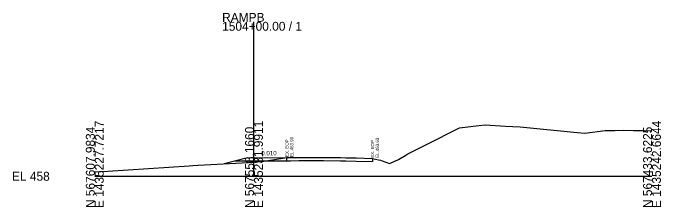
# Model space of a CAD drawing. Extents: x 1431908 to 1449087, y 567604 to 577825.
# Drawn here: x 1439484.4 to 1439688, y 575548.6 to 575609.7 of the extents above; entities that cross this region are included whole.
import ezdxf

# ---------------------------------------------------------------- set-up
doc = ezdxf.new("R2010")
doc.units = 0
for name, color, linetype in [('DESIGN - SHEET - Light Grid', 7, 'Continuous'), ('DESIGN - TYPICAL - Finished Grade and Subgrade', 7, 'Continuous'), ('SURVEY - GROUND - Existing Pavement Layer', 7, 'Continuous'), ('SURVEY - GROUND - Existing Pavement Text', 7, 'Continuous'), ('SURVEY - GROUND - Top of Ground', 7, 'Continuous')]:
    doc.layers.add(name, color=color, linetype=linetype)

msp = doc.modelspace()

# ---------------------------------------------------------------- linework, layer by layer
at = {"layer": 'DESIGN - SHEET - Light Grid'}
for p, q in [((1439560.12, 575558.33), (1439560.12, 575606.94)), ((1439510.12, 575558.33), (1439560.12, 575558.33)), ((1439560.12, 575558.33), (1439685.12, 575558.33))]:
    msp.add_line(p, q, dxfattribs=at)
at = {"layer": 'DESIGN - TYPICAL - Finished Grade and Subgrade'}
for q in [(1439550.81, 575562.28), (1439574.19, 575564.27)]:
    msp.add_line((1439558.12, 575564.11), q, dxfattribs=at)
at = {"layer": 'SURVEY - GROUND - Existing Pavement Layer'}
for p, q in [((1439570.48, 575563.23), (1439570.48, 575564.23)), ((1439597.36, 575563.96), (1439597.36, 575562.96)), ((1439554.24, 575563.14), (1439571.54, 575563.24)), ((1439571.54, 575563.24), (1439574.19, 575563.27)), ((1439574.19, 575563.27), (1439577.6, 575563.27)), ((1439577.6, 575563.27), (1439581.96, 575563.29)), ((1439581.96, 575563.29), (1439587.27, 575563.2)), ((1439587.27, 575563.2), (1439588.96, 575563.17)), ((1439588.96, 575563.17), (1439592.18, 575563.09)), ((1439592.18, 575563.09), (1439597.36, 575562.96))]:
    msp.add_line(p, q, dxfattribs=at)
at = {"layer": 'SURVEY - GROUND - Top of Ground'}
msp.add_lwpolyline([(1439510.12, 575559.7), (1439514.22, 575559.97), (1439539.76, 575561.6), (1439540.95, 575561.7), (1439542.62, 575561.84), (1439558.44, 575562.7), (1439560.12, 575562.8), (1439562.64, 575562.95), (1439569.17, 575564.01), (1439570.48, 575564.23), (1439571.54, 575564.24), (1439574.19, 575564.27), (1439577.6, 575564.27), (1439581.96, 575564.29), (1439587.27, 575564.2), (1439588.96, 575564.17), (1439592.18, 575564.09), (1439597.36, 575563.96), (1439599.28, 575563.54), (1439599.84, 575563.41), (1439600.41, 575563.21), (1439602.66, 575562.39), (1439603.38, 575562.67), (1439605.48, 575563.59), (1439607.83, 575564.98), (1439608.46, 575565.38), (1439614.14, 575568.25), (1439624.65, 575573.61), (1439630.69, 575574.3), (1439632.77, 575574.54), (1439639.09, 575574.15), (1439643.69, 575573.85), (1439661.58, 575572.1), (1439664.04, 575571.86), (1439670.43, 575572.72), (1439673.49, 575572.78), (1439676.15, 575572.83), (1439679.31, 575572.77), (1439682.69, 575572.69), (1439685.12, 575572.62)], dxfattribs=at)

# ---------------------------------------------------------------- texts
at = {"layer": 'DESIGN - SHEET - Light Grid'}
for s, p in [('RAMPB', (1439550.12, 575606.94)), ('1504+00.00 / 1', (1439550.12, 575604.14)), ('EL 458', (1439484.12, 575556.93))]:
    msp.add_text(s, height=2.8, dxfattribs=at).set_placement(p)
for s, p in [('E 1435227.7217', (1439512.92, 575548.33)), ('E 1435231.9911', (1439562.92, 575548.33)), ('E 1435242.6644', (1439687.92, 575548.33)), ('N 567607.9834', (1439510.12, 575548.33)), ('N 567558.1660', (1439560.12, 575548.33)), ('N 567433.6225', (1439685.12, 575548.33))]:
    msp.add_text(s, height=2.8, rotation=90, dxfattribs=at).set_placement(p)
at = {"layer": 'DESIGN - TYPICAL - Finished Grade and Subgrade'}
msp.add_text('0.010', height=1.4, rotation=0.5446, dxfattribs=at).set_placement((1439562.41, 575564.88))
at = {"layer": 'SURVEY - GROUND - Existing Pavement Text'}
for s, p in [('EL.463.90', (1439572.48, 575564.43)), ('EL.463.63', (1439599.36, 575564.16)), ('EX. EOP', (1439570.98, 575564.43)), ('EX. EOP', (1439597.86, 575564.16))]:
    msp.add_text(s, height=1, rotation=90, dxfattribs=at).set_placement(p)

doc.saveas('drawing.dxf')
